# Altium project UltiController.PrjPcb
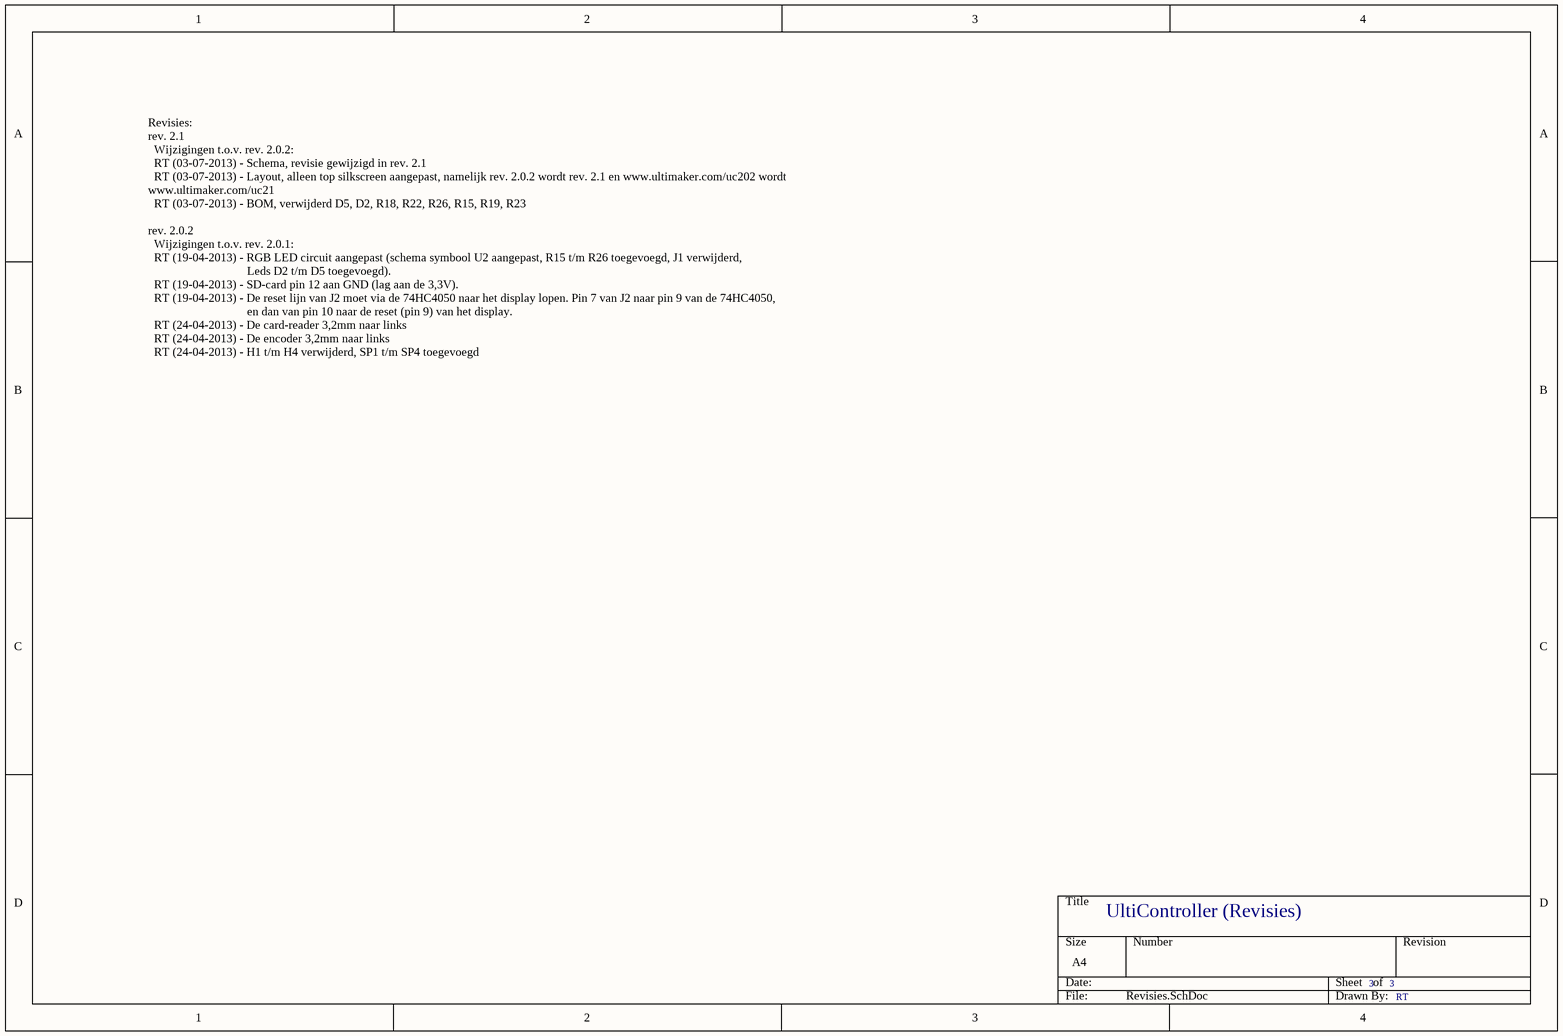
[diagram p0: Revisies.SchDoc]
3 sheets, 131 parts. Net scope: flat (ports and power ports of the same name join across sheets).
Board file: UltiController.PcbDoc
Sheets:
  Revisies.SchDoc
  Sheet1.SchDoc
  Sheet2.SchDoc

## Sheet Revisies.SchDoc
size A4; CompanyName: Ultimaker; Revision: rev. 2.0.2

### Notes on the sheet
- Revisies:
  rev. 2.1
  Wijzigingen t.o.v. rev. 2.0.2:
  RT (03-07-2013) - Schema, revisie gewijzigd in rev. 2.1
  RT (03-07-2013) - Layout, alleen top silkscreen aangepast, namelijk rev. 2.0.2 wordt rev. 2.1 en www.ultimaker.com/uc202 wordt                                      www.ultimaker.com/uc21
  RT (03-07-2013) - BOM, verwijderd D5, D2, R18, R22, R26, R15, R19, R23
  rev. 2.0.2
  Wijzigingen t.o.v. rev. 2.0.1:
  RT (19-04-2013) - RGB LED circuit aangepast (schema symbool U2 aangepast, R15 t/m R26 toegevoegd, J1 verwijderd,
  Leds D2 t/m D5 toegevoegd).
  RT (19-04-2013) - SD-card pin 12 aan GND (lag aan de 3,3V).
  RT (19-04-2013) - De reset lijn van J2 moet via de 74HC4050 naar het display lopen. Pin 7 van J2 naar pin 9 van de 74HC4050,
  en dan van pin 10 naar de reset (pin 9) van het display.
  RT (24-04-2013) - De card-reader 3,2mm naar links
  RT (24-04-2013) - De encoder 3,2mm naar links
  RT (24-04-2013) - H1 t/m H4 verwijderd, SP1 t/m SP4 toegevoegd
- UltiController (Revisies)
- 3
- RT

## Sheet Sheet1.SchDoc
size A4; CompanyName: Ultimaker; Revision: rev. 2.1
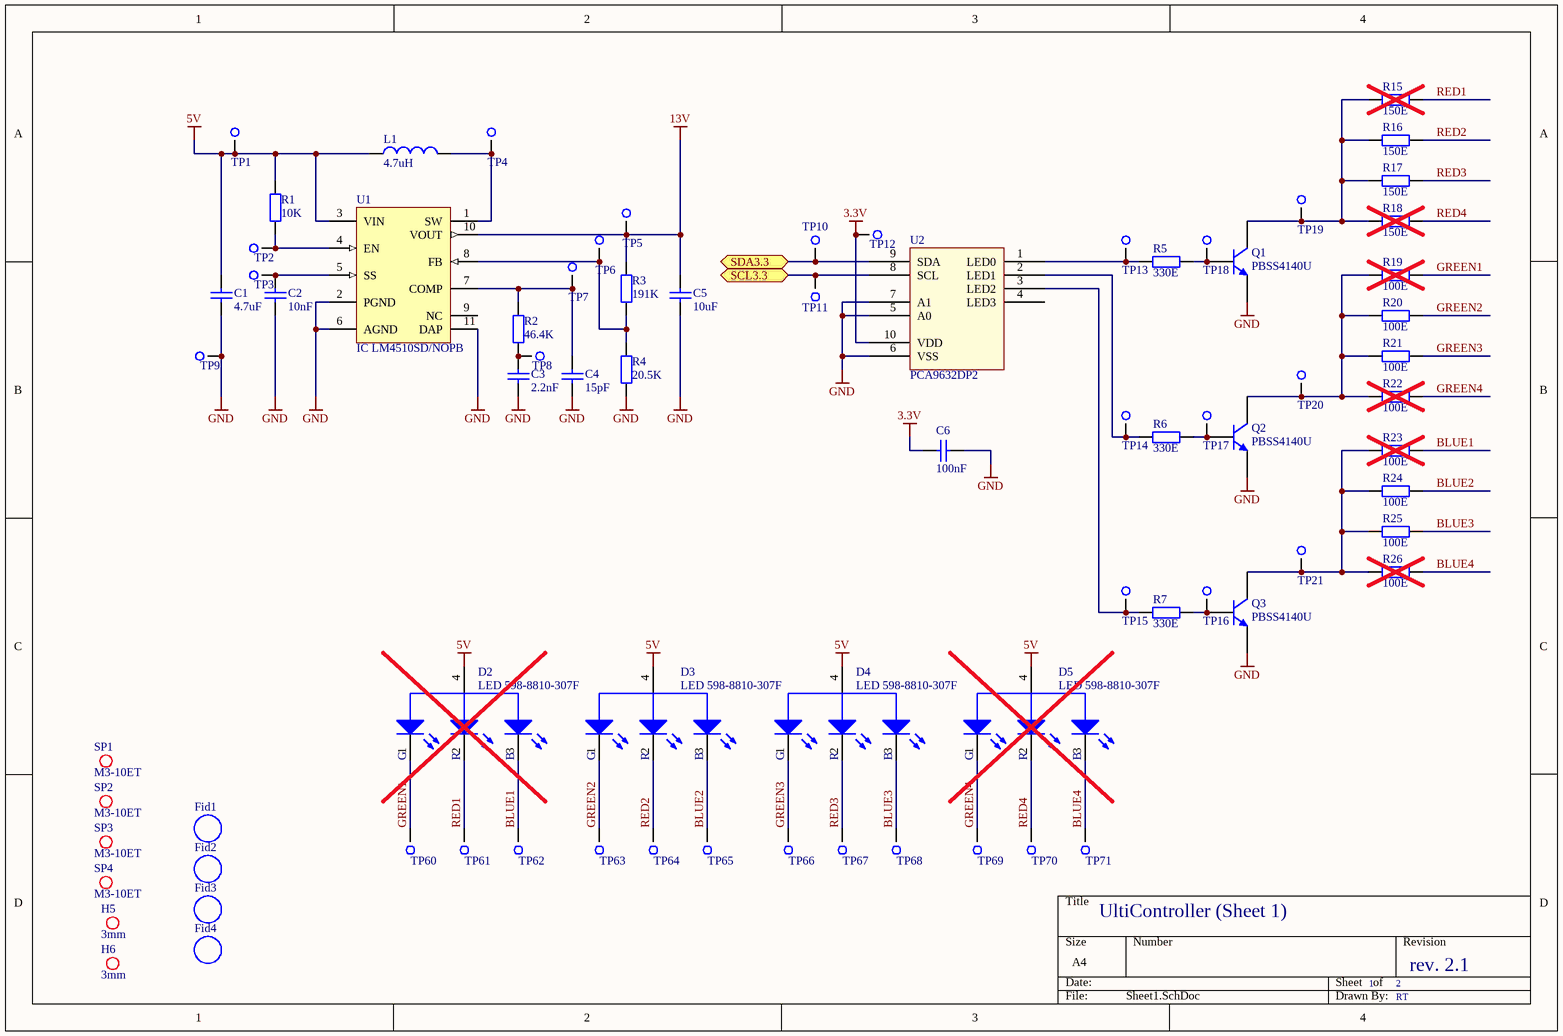
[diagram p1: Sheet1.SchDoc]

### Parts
C1  4.7uF  [C1206 (3216)]
C2  10nF  [C0805 (2012)]
C3  2.2nF  [C0805 (2012)]
C4  15pF  [C0805 (2012)]
C5  10uF  [C1206 (3216)]
C6  100nF  [C0805 (2012)]
D2  LED 598-8810-307F  [LED SMD  598-8810-307F]  (no BOM)
D3  LED 598-8810-307F  [LED SMD  598-8810-307F]
D4  LED 598-8810-307F  [LED SMD  598-8810-307F]
D5  LED 598-8810-307F  [LED SMD  598-8810-307F]  (no BOM)
Fid1  Fiducial  [Fiducial 1,5mm]  (value not drawn)  (no BOM)
Fid2  Fiducial  [Fiducial 1,5mm]  (value not drawn)  (no BOM)
Fid3  Fiducial  [Fiducial 1,5mm]  (value not drawn)  (no BOM)
Fid4  Fiducial  [Fiducial 1,5mm]  (value not drawn)  (no BOM)
H5  3mm  [Mounting Hole 3mm PTH]  (no BOM)
H6  3mm  [Mounting Hole 3mm PTH]  (no BOM)
L1  4.7uH  [Inductor MCSDC0604]
Q1  PBSS4140U  [IC SOT323]
Q2  PBSS4140U  [IC SOT323]
Q3  PBSS4140U  [IC SOT323]
R1  10K  [R0805 (2012)]
R2  46.4K  [R0805 (2012)]
R3  191K  [R0805 (2012)]
R4  20.5K  [R0805 (2012)]
R5  330E  [R0805 (2012)]
R6  330E  [R0805 (2012)]
R7  330E  [R0805 (2012)]
R15  150E  [R0805 (2012)]  (no BOM)
R16  150E  [R0805 (2012)]
R17  150E  [R0805 (2012)]
R18  150E  [R0805 (2012)]  (no BOM)
R19  100E  [R0805 (2012)]  (no BOM)
R20  100E  [R0805 (2012)]
R21  100E  [R0805 (2012)]
R22  100E  [R0805 (2012)]  (no BOM)
R23  100E  [R0805 (2012)]  (no BOM)
R24  100E  [R0805 (2012)]
R25  100E  [R0805 (2012)]
R26  100E  [R0805 (2012)]  (no BOM)
SP1  M3-10ET  [Spacer M3-10ET]
SP2  M3-10ET  [Spacer M3-10ET]
SP3  M3-10ET  [Spacer M3-10ET]
SP4  M3-10ET  [Spacer M3-10ET]
TP1  2mm  [TESTPOINT 2mm]  (value not drawn)  (no BOM)
TP2  2mm  [TESTPOINT 2mm]  (value not drawn)  (no BOM)
TP3  2mm  [TESTPOINT 2mm]  (value not drawn)  (no BOM)
TP4  2mm  [TESTPOINT 2mm]  (value not drawn)  (no BOM)
TP5  2mm  [TESTPOINT 2mm]  (value not drawn)  (no BOM)
TP6  2mm  [TESTPOINT 2mm]  (value not drawn)  (no BOM)
TP7  2mm  [TESTPOINT 2mm]  (value not drawn)  (no BOM)
TP8  2mm  [TESTPOINT 2mm]  (value not drawn)  (no BOM)
TP9  2mm  [TESTPOINT 2mm]  (value not drawn)  (no BOM)
TP10  2mm  [TESTPOINT 2mm]  (value not drawn)  (no BOM)
TP11  2mm  [TESTPOINT 2mm]  (value not drawn)  (no BOM)
TP12  2mm  [TESTPOINT 2mm]  (value not drawn)  (no BOM)
TP13  2mm  [TESTPOINT 2mm]  (value not drawn)  (no BOM)
TP14  2mm  [TESTPOINT 2mm]  (value not drawn)  (no BOM)
TP15  2mm  [TESTPOINT 2mm]  (value not drawn)  (no BOM)
TP16  2mm  [TESTPOINT 2mm]  (value not drawn)  (no BOM)
TP17  2mm  [TESTPOINT 2mm]  (value not drawn)  (no BOM)
TP18  2mm  [TESTPOINT 2mm]  (value not drawn)  (no BOM)
TP19  2mm  [TESTPOINT 2mm]  (value not drawn)  (no BOM)
TP20  2mm  [TESTPOINT 2mm]  (value not drawn)  (no BOM)
TP21  2mm  [TESTPOINT 2mm]  (value not drawn)  (no BOM)
TP60  2mm  [TESTPOINT 2mm]  (value not drawn)  (no BOM)
TP61  2mm  [TESTPOINT 2mm]  (value not drawn)  (no BOM)
TP62  2mm  [TESTPOINT 2mm]  (value not drawn)  (no BOM)
TP63  2mm  [TESTPOINT 2mm]  (value not drawn)  (no BOM)
TP64  2mm  [TESTPOINT 2mm]  (value not drawn)  (no BOM)
TP65  2mm  [TESTPOINT 2mm]  (value not drawn)  (no BOM)
TP66  2mm  [TESTPOINT 2mm]  (value not drawn)  (no BOM)
TP67  2mm  [TESTPOINT 2mm]  (value not drawn)  (no BOM)
TP68  2mm  [TESTPOINT 2mm]  (value not drawn)  (no BOM)
TP69  2mm  [TESTPOINT 2mm]  (value not drawn)  (no BOM)
TP70  2mm  [TESTPOINT 2mm]  (value not drawn)  (no BOM)
TP71  2mm  [TESTPOINT 2mm]  (value not drawn)  (no BOM)
U1  IC LM4510SD/NOPB  [IC SDA10A]
U2  PCA9632DP2  [IC TSSOP-10]

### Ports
SCL3.3 (bidir), SDA3.3 (bidir)

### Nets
3.3V: C6.1 TP12.1 U2.10(VDD)
5V: C1.2 D2.4 D3.4 D4.4 D5.4 L1.1 R1.2 TP1.1 U1.3(VIN)
13V: C5.2 R3.2 TP5.1 U1.10(VOUT)
GND: C1.1 C2.1 C3.1 C4.1 C5.1 C6.2 Q1.2(E) Q2.2(E) Q3.2(E) R4.1 TP9.1 U1.2(PGND) U1.6(AGND) U1.11(DAP) U2.5(A0) U2.6(VSS) U2.7(A1)
BLUE1: D2.3 R23.2 TP62.1
BLUE2: D3.3 R24.2 TP65.1
BLUE3: D4.3 R25.2 TP68.1
BLUE4: D5.3 R26.2 TP71.1
GREEN1: D2.1 R19.2 TP60.1
GREEN2: D3.1 R20.2 TP63.1
GREEN3: D4.1 R21.2 TP66.1
GREEN4: D5.1 R22.2 TP69.1
RED1: D2.2 R15.2 TP61.1
RED2: D3.2 R16.2 TP64.1
RED3: D4.2 R17.2 TP67.1
RED4: D5.2 R18.2 TP70.1
NetC2_2: C2.2 TP3.1 U1.5(SS)
NetC3_2: C3.2 R2.1 TP8.1
NetC4_2: C4.2 R2.2 TP7.1 U1.7(COMP)
NetJ6_13: TP11.1 U2.8(SCL) ; port SCL3.3
NetJ6_14: TP10.1 U2.9(SDA) ; port SDA3.3
NetL1_2: L1.2 TP4.1 U1.1(SW)
NetQ1_1: Q1.1(B) R5.2 TP18.1
NetQ1_3: Q1.3(C) R15.1 R16.1 R17.1 R18.1 TP19.1
NetQ2_1: Q2.1(B) R6.2 TP17.1
NetQ2_3: Q2.3(C) R19.1 R20.1 R21.1 R22.1 TP20.1
NetQ3_1: Q3.1(B) R7.2 TP16.1
NetQ3_3: Q3.3(C) R23.1 R24.1 R25.1 R26.1 TP21.1
NetR1_1: R1.1 TP2.1 U1.4(EN)
NetR3_1: R3.1 R4.2 TP6.1 U1.8(FB)
NetR5_1: R5.1 TP13.1 U2.1(LED0)
NetR6_1: R6.1 TP14.1 U2.2(LED1)
NetR7_1: R7.1 TP15.1 U2.3(LED2)

Not connected (* = marked no-connect by the designer): U1 9(NC); U2 4(LED3)

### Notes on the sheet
- UltiController (Sheet 1)
- 1
- 2
- rev. 2.1
- RT

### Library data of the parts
C1 = Cap 4.7uF X7R 1206: Cap 4.7uF 1206 X7R 10% 25V; Mfg: TDK; Mfg code: C3216X7R1E475K160AC
C2 = Cap 10nF X7R 0805: Cap 10nF X7R 0805 10% 100V; Mfg: AVX; Mfg code: 08051C103K4Z2A
C3 = Cap 2.2nF X7R 0805: Cap 2.2nF X7R 0805 10% 100V; Mfg: KEMET; Mfg code: C0805F222K1RACAUTO
C4 = Cap 15pF NPO 0805: Cap 15pF NPO 0805 5% 100V; Mfg: AVX; Mfg code: 08051A150JAT2A
C5 = Cap 10uF X7R 1206: Cap 10uF 1206 X7R 10% 25V; Mfg: KEMET; Mfg code: C1206C106K3RAC TU
C6 = Cap 100nF X7R 0805: Cap 100nF X7R 0805 10% 100V; Mfg: AVX; Mfg code: 08051C104K4T2A
D2-D5 = LED 598-8810-307F: LED MULTICOLOR RED/GRN/BLUE 1208; Mfg: DIALIGHT; Bestel grote: 1; Prijs: 2.26
Fid1-Fid4 = Fiducial: Remarks: Not a component
H5 H6 = Mounting Hole 3mm PTH: Remarks: Not a component
L1 = Inductor 4.7uH SMD: Mfg: MULTICOMP; Mfg code: MCSDC0604-4R7MU
Q1-Q3 = NPN PBSS4140U: NPN PBSS4140U SOT-323 1A; Mfg: NXP
R1 = Res 10K 0805: Res 10K 0805 1% 100mW; Mfg: MULTICOMP; Mfg code: MC 0.1W 0805 1% 10K
R2 = Res 46.4K 0805: Res 46.4K 0805 1% 100mW; Mfg: MULTICOMP; Mfg code: MC0.1W08051%46K4
R3 = Res 191K 0805: Res 191K 0805 1% 125mW; Mfg: VISHAY DRALORIC; Mfg code: CRCW0805191KFKEA
R4 = Res 20.5K 0805: Res 20.5K 0805 1% 100mW; Mfg: MULTICOMP; Mfg code: MC0.1W08051%20K5
R5-R7 = Res 330E 0805: Res 330E 0805 1% 100mW; Mfg: MULTICOMP; Mfg code: MC 0.1W 0805 1% 330R
R15-R18 = Res 150E 0805: Res 150E 0805 1% 125mW; Faber ItemCode: 31224600; Mfg: YAGEO; Mfg code: 2322 734 61501; Faber Artikelomschrijving: RES 150E 1% 0,125W 0805; Bestel grote: 5000; Prijs: 0,0012
R19-R26 = Res 100E 0805: Res 100E 0805 1% 125mW; Faber ItemCode: 31560100; Mfg: YAGEO; Mfg code: WRC31022/ RC0805FR-07100RL; Faber Artikelomschrijving: RES 100E 1% 0,125W 0805; Bestel grote: 5000; Prijs: 0,0009
SP1-SP4 = Spacer M3-10ET: Spacer SMTSO-M3-10ET; Faber ItemCode: 36462900; Mfg: PEM; Faber Artikelomschrijving: MOER-SMD SMTSO-M3-10ET  PEM; Bestel grote: 300; Prijs: 0.4311
TP1-TP21 TP60-TP71 = Testpoint, 2mm, round: Remarks: Not a component
U1 = IC LM4510SD/NOPB: IC Synchronous Step-Up DC/DC Converter with True Shutdown Isolation, 10-pin LLP, Pb-Free; Faber ItemCode: 36966700; Mfg: TEXAS INSTRUMENTS; Faber Artikelomschrijving: IC LM4510SD/NOPB LLP-10 TI; Bestel grote: 1; Prijs: 1,10
U2 = IC PCA9632: IC LED DRIVER RGBA; Faber ItemCode: 36966800; Mfg: NXP; Faber Artikelomschrijving: IC PCA9632DP2 TSSOP-10 NXP; Bestel grote: 1000; Prijs: 1,0876

## Sheet Sheet2.SchDoc
size A4; CompanyName: Ultimaker; Revision: rev. 2.0.2
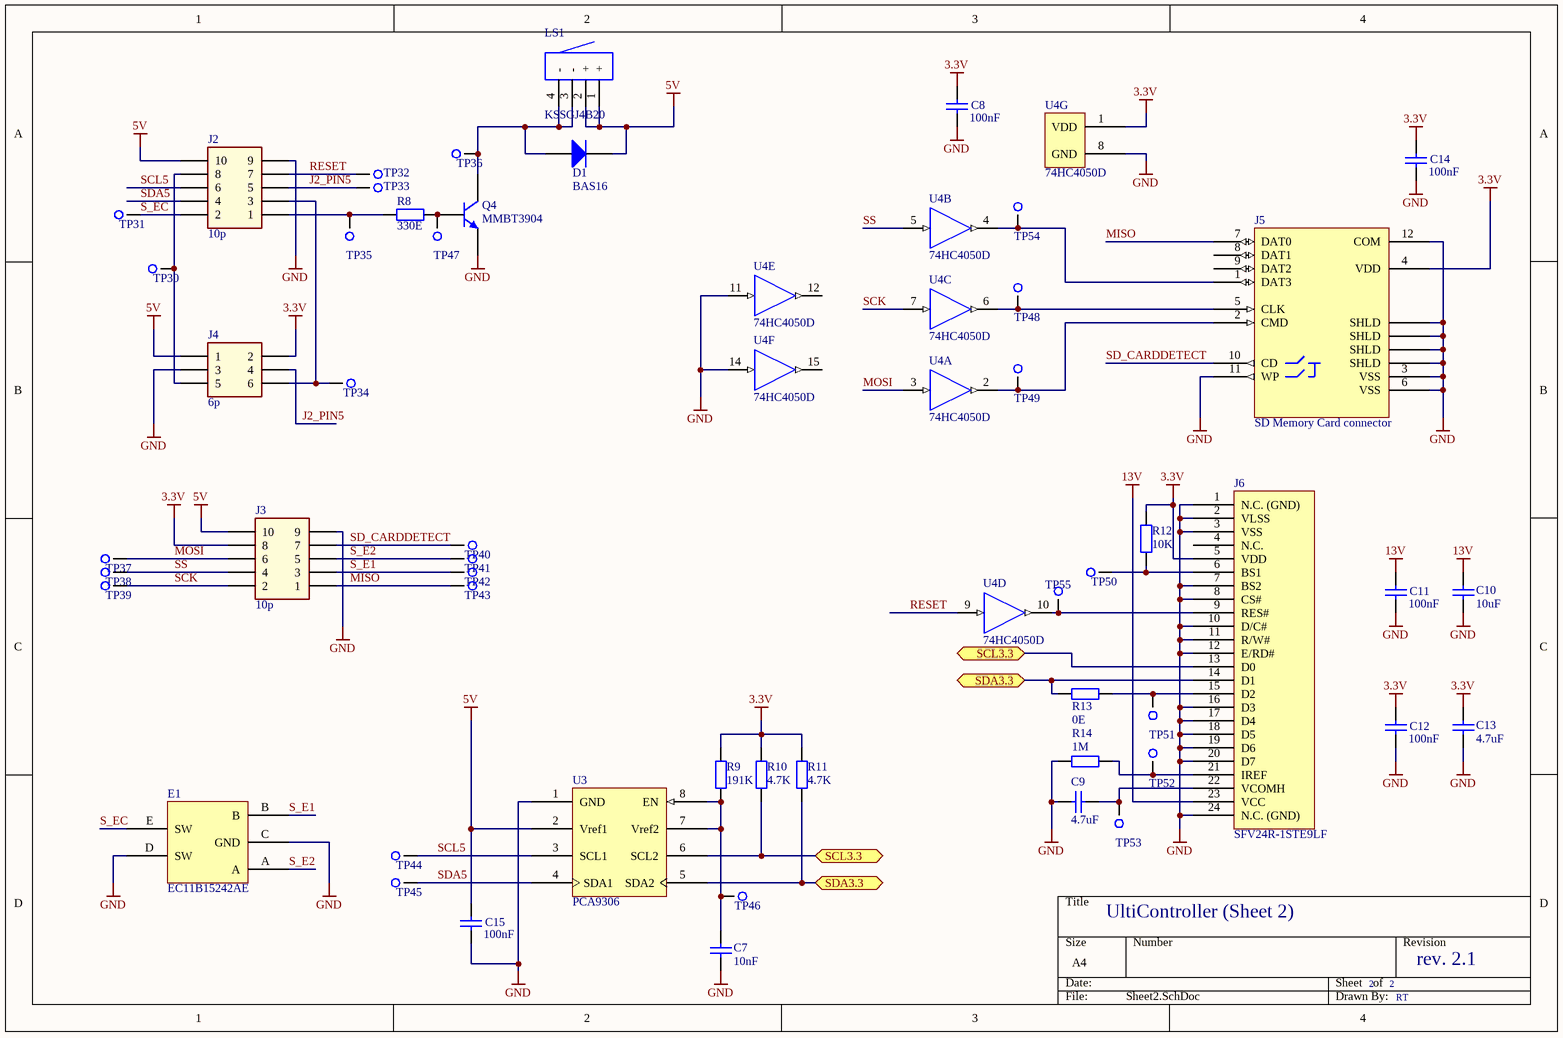
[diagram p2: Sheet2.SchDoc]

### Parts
C7  10nF  [C0805 (2012)]
C8  100nF  [C0805 (2012)]
C9  4.7uF  [C1206 (3216)]
C10  10uF  [C1206 (3216)]
C11  100nF  [C0805 (2012)]
C12  100nF  [C0805 (2012)]
C13  4.7uF  [C1206 (3216)]
C14  100nF  [C0805 (2012)]
C15  100nF  [C0805 (2012)]
D1  BAS16  [IC SOT23]
E1  EC11B15242AE  [Misc EC11B15242AE]
J2  10p  [HEADER 10P right angle]
J3  10p  [HEADER 10P right angle]
J4  6p  [HEADER 6P RIGHT ANGLE]
J5  SD Memory Card connector  [CON SD-Card]
J6  SFV24R-1STE9LF  [Con SFV24R-1STE9LF]
LS1  KSSGJ4B20  [Buzzer KSSGJ4B20]
Q4  MMBT3904  [IC SOT23]
R8  330E  [R0805 (2012)]
R9  191K  [R0805 (2012)]
R10  4.7K  [R0805 (2012)]
R11  4.7K  [R0805 (2012)]
R12  10K  [R0805 (2012)]
R13  0E  [R0805 (2012)]
R14  1M  [R0805 (2012)]
TP30  2mm  [TESTPOINT 2mm]  (value not drawn)  (no BOM)
TP31  2mm  [TESTPOINT 2mm]  (value not drawn)  (no BOM)
TP32  2mm  [TESTPOINT 2mm]  (value not drawn)  (no BOM)
TP33  2mm  [TESTPOINT 2mm]  (value not drawn)  (no BOM)
TP34  2mm  [TESTPOINT 2mm]  (value not drawn)  (no BOM)
TP35  2mm  [TESTPOINT 2mm]  (value not drawn)  (no BOM)
TP36  2mm  [TESTPOINT 2mm]  (value not drawn)  (no BOM)
TP37  2mm  [TESTPOINT 2mm]  (value not drawn)  (no BOM)
TP38  2mm  [TESTPOINT 2mm]  (value not drawn)  (no BOM)
TP39  2mm  [TESTPOINT 2mm]  (value not drawn)  (no BOM)
TP40  2mm  [TESTPOINT 2mm]  (value not drawn)  (no BOM)
TP41  2mm  [TESTPOINT 2mm]  (value not drawn)  (no BOM)
TP42  2mm  [TESTPOINT 2mm]  (value not drawn)  (no BOM)
TP43  2mm  [TESTPOINT 2mm]  (value not drawn)  (no BOM)
TP44  2mm  [TESTPOINT 2mm]  (value not drawn)  (no BOM)
TP45  2mm  [TESTPOINT 2mm]  (value not drawn)  (no BOM)
TP46  2mm  [TESTPOINT 2mm]  (value not drawn)  (no BOM)
TP47  2mm  [TESTPOINT 2mm]  (value not drawn)  (no BOM)
TP48  2mm  [TESTPOINT 2mm]  (value not drawn)  (no BOM)
TP49  2mm  [TESTPOINT 2mm]  (value not drawn)  (no BOM)
TP50  2mm  [TESTPOINT 2mm]  (value not drawn)  (no BOM)
TP51  2mm  [TESTPOINT 2mm]  (value not drawn)  (no BOM)
TP52  2mm  [TESTPOINT 2mm]  (value not drawn)  (no BOM)
TP53  2mm  [TESTPOINT 2mm]  (value not drawn)  (no BOM)
TP54  2mm  [TESTPOINT 2mm]  (value not drawn)  (no BOM)
TP55  2mm  [TESTPOINT 2mm]  (value not drawn)  (no BOM)
U3  PCA9306  [IC SSOP-8]
U4  74HC4050D  [IC SOIC-16]  (parts A,B,C,D,E,F,G of 7)

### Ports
SCL3.3 (bidir), SDA3.3 (bidir)

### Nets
3.3V: C8.2 C12.2 C13.1 C14.2 J3.8 J4.2 J5.4(VDD) J6.5(VDD) R9.2 R10.2 R11.2 R12.2 U4.1(VDD)
5V: C15.2 D1.3(K) J2.10 J3.10 J4.1 LS1.1(+) LS1.2(+) U3.2(Vref1)
13V: C10.2 C11.2 J6.23(VCC)
GND: C7.1 C8.1 C9.2 C10.1 C11.1 C12.1 C13.2 C14.1 C15.1 E1.C(GND) E1.D(SW) J2.9 J3.9 J4.3 J5.3(VSS) J5.6(VSS) J5.11(WP) J5.12(COM) J5.A(SHLD) J5.B(SHLD) J5.C(SHLD) J5.D(SHLD) J6.1(N.C._(GND)) J6.2(VLSS) J6.3(VSS) J6.7(BS2) J6.8(CS#) J6.10(D/C#) J6.11(R/W#) J6.12(E/RD#) J6.16(D3) J6.17(D4) J6.18(D5) J6.19(D6) J6.20(D7) J6.24(N.C._(GND)) Q4.2(E) R14.1 U3.1(GND) U4.8(GND) U4.11(A) U4.14(A)
J2_PIN5: J2.5 J4.4 TP33.1
MISO: J3.1 J5.7(DAT0) TP43.1
MOSI: J3.6 TP37.1 U4.3(A)
RESET: J2.7 TP32.1 U4.9(A)
S_E1: E1.B J3.3 TP42.1
S_E2: E1.A J3.5 TP41.1
S_EC: E1.E(SW) J2.2 TP31.1
SCK: J3.2 TP39.1 U4.7(A)
SCL5: J2.6 TP44.1 U3.3(SCL1)
SD_CARDDETECT: J3.7 J5.10(CD) TP40.1
SDA5: J2.4 TP45.1 U3.4(SDA1)
SS: J3.4 TP38.1 U4.5(A)
NetC7_2: C7.2 R9.1 TP46.1 U3.7(Vref2) U3.8(EN)
NetC9_1: C9.1 J6.22(VCOMH) TP53.1
NetD1_1: D1.1(A) LS1.3(-) LS1.4(-) Q4.3(C) TP36.1
NetJ2_1: J2.1 R8.1 TP35.1
NetJ2_3: J2.3 J4.6 TP34.1
NetJ2_8: J2.8 J4.5 TP30.1
NetJ5_1: J5.1(DAT3) TP54.1 U4.4(Y)
NetJ5_2: J5.2(CMD) TP49.1 U4.2(Y)
NetJ5_5: J5.5(CLK) TP48.1 U4.6(Y)
NetJ6_6: J6.6(BS1) R12.1 TP50.1
NetJ6_9: J6.9(RES#) TP55.1 U4.10(Y)
NetJ6_13: J6.13(D0) R10.1 U3.6(SCL2) ; port SCL3.3
NetJ6_14: J6.14(D1) R11.1 R13.1 U3.5(SDA2) ; port SDA3.3
NetJ6_15: J6.15(D2) R13.2 TP51.1
NetJ6_21: J6.21(IREF) R14.2 TP52.1
NetQ4_1: Q4.1(B) R8.2 TP47.1

Not connected (* = marked no-connect by the designer): J5 8(DAT1) 9(DAT2); J6 4(N.C.); U4 12(Y) 15(Y)

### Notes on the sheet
- UltiController (Sheet 2)
- 2
- rev. 2.1
- RT

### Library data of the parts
C7 = Cap 10nF X7R 0805: as C2 on sheet Sheet1
C8 C11 C12 C14 C15 = Cap 100nF X7R 0805: as C6 on sheet Sheet1
C9 C13 = Cap 4.7uF X7R 1206: as C1 on sheet Sheet1
C10 = Cap 10uF X7R 1206: as C5 on sheet Sheet1
D1 = Diode BAS16: Diode BAS16  SOT23 85V 215MA; Mfg: NXP
E1 = Misc EC11B15242AE: Misc EC11B15242AE encoder horiz; Mfg: ALPS
J2 J3 = Header 10p: Header 2x5p right angle 2.54mm; Mfg: WURTH ELEKTRONIK; Mfg code: 61201021721
J4 = Header 6p r.a.: Header 2x3p right angle 2.54mm; Mfg: FCI; Mfg code: 68021-206HLF
J5 = Connector SD-Card-Hirose: Connector Std,reverse SD Memory Card connector; Faber ItemCode: 36966100; Mfg: HRS (HIROSE); Mfg code: DM1AA-SF-PEJ(72); Faber Artikelomschrijving: SD-KAARDHOUDER SMD DM1AA-SF-PEJ(72) HIROSE; Bestel grote: 1; Prijs: 3,02
J6 = Connector SFV24R-1STE9LF: Connector FPC/FFC 0.5mm R/A 24p SMD; Mfg: FCI
LS1 = Buzzer KSSGJ4B20: Buzzer KSSGJ4B20 SMD; Mfg: KINGSTATE
Q4 = NPN MMBT3904: NPN MMBT3904 SOT-23 200mA; Mfg: NXP; Mfg code: MMBT3904,215
R8 = Res 330E 0805: as R5 on sheet Sheet1
R9 = Res 191K 0805: as R3 on sheet Sheet1
R10 R11 = Res 4.7K 0805: Res 4.7K 0805 1% 100mW; Mfg: MULTICOMP; Mfg code: MC 0.1W 0805 1% 4K7
R12 = Res 10K 0805: as R1 on sheet Sheet1
R13 = Res 0E 0805: Res 0E 0805 1% 100mW; Mfg: MULTICOMP; Mfg code: MC 0.1W 0805 0R
R14 = Res 1M 0805: Res 1M 0805 1% 100mW; Mfg: MULTICOMP; Mfg code: MC 0.1W 0805 1% 1M
TP30-TP55 = Testpoint, 2mm, round: Remarks: Not a component
U3 = IC PCA9306: IC PCA9306 Voltage Level translator; Mfg: TEXAS INSTRUMENTS; Mfg code: PCA9306DCTR
U4 = IC 74HC4050D: IC Hex Non-Inverting Buffer/Logic-Level Down Converter; Faber ItemCode: 35592900; Mfg: NXP; Faber Artikelomschrijving: IC 74HC4050D SO-16 NXP; Bestel grote: 2500; Prijs: 0,0878

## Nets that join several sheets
3.3V: Sheet1 (C6.1 TP12.1 U2.10), Sheet2 (13 pins)
5V: Sheet1 (9 pins), Sheet2 (8 pins)
13V: Sheet1 (C5.2 R3.2 TP5.1 U1.10), Sheet2 (C10.2 C11.2 J6.23)
GND: Sheet1 (17 pins), Sheet2 (42 pins)
NetJ6_13: Sheet1 (TP11.1 U2.8), Sheet2 (J6.13 R10.1 U3.6)
NetJ6_14: Sheet1 (TP10.1 U2.9), Sheet2 (J6.14 R11.1 R13.1 U3.5)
